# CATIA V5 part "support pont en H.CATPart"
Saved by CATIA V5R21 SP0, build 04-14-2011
Part number: H
Bounding box of the stored display mesh (mm): x 0 to 129, y -15 to 60, z 0 to 9
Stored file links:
  C:\Users\2027.DESARCY-LEMIE30\Desktop\Assemblage26.05\support pont en H.CATPart
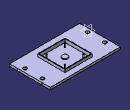
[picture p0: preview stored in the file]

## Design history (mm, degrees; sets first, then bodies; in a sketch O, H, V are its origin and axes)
Body1 (main body)
  Sketch1 on xy-plane, origin (0, 0, 0), H (1, 0, 0), V (0, 1, 0)
    construction line L1 (0, 0) -> (129, 0)
    line L2 (129, 0) -> (129, 45)
    construction line L3 (129, 45) -> (0, 45)
    line L4 (0, 45) -> (0, 0)
    line L5 (129, 45) -> (129, 60)
    line L6 (129, 0) -> (129, -15)
    line L7 (129, -15) -> (0, -15)
    point P6 (0, -15)
    line L8 (129, 60) -> (0, 60)
    point P7 (0, 60)
    line L9 (0, 60) -> (0, 45)
    line L10 (0, -15) -> (0, 0)
    length L2 = 45
    length L3 = 129
    length L5 = 15
    length L6 = 15
    horizontal: L1 H, L3 H, L7 H, L8 H
    vertical: L2 V, L4 V, L5 V, L6 V, L9 V, L10 V
    coincidence: P6 L4, P7 V
  Pad1: profile Sketch1, direction (0, 0, 1), length 4
  Sketch2 on end face of Pad1, origin (0, 0, 4), H (1, 0, 0), V (0, 1, 0)
    line L1 (42, 50) -> (92, 50)
    line L2 (92, 50) -> (92, 0)
    line L3 (92, 0) -> (42, 0)
    line L4 (42, 0) -> (42, 50)
    point P3 (92, 0)
    reference projected line E1 (0, 45) -> (0, 0) from edge [face of Pad1 from Sketch1.L4 | end face of Pad1]
    distance L4 E1 = 42
    distance L1 H = 50
    length L1 = 50
    horizontal: L1 H, L3 H
    vertical: L2 V, L4 V
    coincidence: P3 H
  Pad2: profile Sketch2, direction (0, 0, 1), length 5
  Sketch3 on end face of Pad2, origin (0, 0, 9), H (1, 0, 0), V (0, 1, 0)
    line L1 (43, 49) -> (91, 49)
    line L2 (91, 49) -> (91, 1)
    line L3 (91, 1) -> (43, 1)
    line L4 (43, 1) -> (43, 49)
    reference projected line E1 (92, 50) -> (42, 50) from edge [face of Pad2 from Sketch2.L1 | end face of Pad2]
    reference projected line E2 (92, 0) -> (92, 50) from edge [face of Pad2 from Sketch2.L2 | end face of Pad2]
    reference projected line E3 (42, 0) -> (92, 0) from edge [face of Pad2 from Sketch2.L3 | end face of Pad2]
    reference projected line E4 (42, 50) -> (42, 0) from edge [face of Pad2 from Sketch2.L4 | end face of Pad2]
    distance L1 E1 = 1
    distance L2 E2 = 1
    distance L3 E3 = 1
    distance L4 E4 = 1
    horizontal: L1 H, L3 H
    vertical: L2 V, L4 V
  Pocket1: profile Sketch3, direction (0, 0, -1), length 6
  Sketch4 on end face of Pocket1, origin (0, 0, 3), H (1, 0, 0), V (0, 1, 0)
    circle A1 centre (50.1844, 42.0334) radius 1
    construction line L1 (50.1844, 42.0334) -> (84.1844, 42.0334)
    point P1 (50.1844, 42.0334)
    circle A2 centre (84.1844, 42.0334) radius 1
    construction line L2 (84.1844, 42.0334) -> (84.1844, 8.0334)
    circle A3 centre (84.1844, 8.0334) radius 1
    construction line L3 (50.1844, 42.0334) -> (50.1844, 8.0334)
    circle A4 centre (50.1844, 8.0334) radius 1
    construction line L4 (60.1354, 32.0176) -> (74.2335, 18.0492)
    construction line L5 (50.1844, 8.0334) -> (84.1844, 42.0334)
    point P7 (67.1844, 25.0334)
    point P8 (67.1844, 25.0334)
    radius A1 = 1
    radius A2 = 1
    length L2 = 34
    radius A3 = 1
    radius A4 = 1
    length L3 = 34
    length L1 = 34
    concentricity: P1 A1
    horizontal: L1 H
    vertical: L2 V, L3 V
    midpoint: P7 L5, P8 L4
    fix: L4
    coincidence: P8 P7
  Pad3: profile Sketch4, direction (0, 0, 1), length 6
  Sketch5 on end face of Pocket1, origin (0, 0, 3), H (1, 0, 0), V (0, 1, 0)
    circle A1 centre (67, 25) radius 5
    construction line L1 (43, 49) -> (91, 1)
    point P1 (43, 49)
    point P2 (91, 1)
    reference projected point E1 (91, 1) from vertex [face of Pocket1 from Sketch3.L3 | face of Pocket1 from Sketch3.L2 | end face of Pad2]
    reference projected point E2 (43, 49) from vertex [face of Pocket1 from Sketch3.L4 | face of Pocket1 from Sketch3.L1 | end face of Pad2]
    point P3 (67, 25)
    radius A1 = 5
    coincidence: P2 E1, P1 E2
    midpoint: P3 L1
    concentricity: A1 P3
  Pad4: profile Sketch5, direction (0, 0, 1), length 2
  Sketch6 on end face of Pad1, origin (0, 0, 4), H (1, 0, 0), V (0, 1, 0)
    circle A1 centre (7, 6.5) radius 3.5
    circle A2 centre (7, 38.5) radius 3.5
    circle A3 centre (122, 38.5) radius 3.5
    circle A4 centre (122, 6.5) radius 3.5
    radius A1 = 3.5
  Pocket2: profile Sketch6, direction (0, 0, -1), through (limit type 6)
